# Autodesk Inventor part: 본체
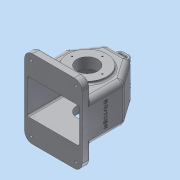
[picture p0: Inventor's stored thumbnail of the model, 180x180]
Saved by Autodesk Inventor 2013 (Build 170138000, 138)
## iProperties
Created: 2016-12
Part Number: 본체
Material: 알루미늄 6061
Document SubType Name: Modeling
Designer: dgall
Density: 2.71 g/cm^3
Mass: 1017.32 g
Surface Area: 1124 cm^2
Volume: 375.394 cm^3
Author: dgall
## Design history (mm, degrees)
sketch "스케치1"
  geometry: L1 (-55, -65)-(55, -65); L2 (55, -65)-(55, 15); L3 (55, 15)-(23.491, 60); L4 (23.491, 60)-(-23.491, 60); L5 (-23.491, 60)-(-55, 15); L6 (-55, 15)-(-55, -65); 2 further points
  constraints: 12 end point, 1 horizontal, 1 horizontal alignment, 1 midpoint, 1 parallel, 1 perpendicular, 1 vertical, 1 vertical alignment
  dimensions: "d0" = 35 deg angle of L6 L5; "d1" = 35 deg angle of L2 L3; "d2" = 80 distance from line of L2.end L1; "d4" = 125 distance between parallel lines of L1 L4; "d5" = 110 distance of L1.start L1.end; "d6" = 65 distance from line of L1 point (0, 0)
extrude "돌출1" new body sketch "스케치1" distance "d7" = 5; taper "d8" = 0 deg
sketch "스케치2"
  geometry: L1 (-55, -65)-(55, -65) reference; L2 (55, -65)-(55, 15) reference; L3 (55, 15)-(23.491, 60) reference; L4 (23.491, 60)-(-23.491, 60) reference; L5 (-23.491, 60)-(-55, 15) reference; L6 (-55, 15)-(-55, -65) reference; L7 (-55, -65)-(55, -65) reference; L8 (55, -65)-(55, 15) reference; L9 (55, 15)-(23.491, 60) reference; L10 (23.491, 60)-(-23.491, 60) reference; L11 (-23.491, 60)-(-55, 15) reference; L12 (-55, 15)-(-55, -65) reference; L13 (20.888, 55)-(50, 13.424); L14 (50, 13.424)-(50, -60); L15 (50, -60)-(-50, -60); L16 (-50, -60)-(-50, 13.424); L17 (-50, 13.424)-(-20.888, 55); L18 (-20.888, 55)-(20.888, 55); 1 further point
  constraints: 12 end point, 5 other
  dimensions: "d9" = 5 distance between parallel lines of L18 L4
extrude "돌출2" join sketch "스케치2" distance "d10" = 67; taper "d11" = 0 deg
sketch "스케치3"
  geometry: L1 (50, 13.424)-(50, -60) reference; L2 (50, -60)-(-50, -60) reference; L3 (-50, -60)-(-50, 13.424) reference; L4 (-50, 13.424)-(-20.888, 55) reference; L5 (-20.888, 55)-(20.888, 55) reference; L6 (20.888, 55)-(50, 13.424) reference; L7 (-55, -65)-(55, -65) reference; L8 (55, -65)-(55, 15) reference; L9 (55, 15)-(23.491, 60) reference; L10 (23.491, 60)-(-23.491, 60) reference; L11 (-23.491, 60)-(-55, 15) reference; L12 (-55, 15)-(-55, -65) reference; 1 further point
extrude "돌출3" join sketch "스케치3" distance "d12" = 5; taper "d13" = 0 deg
sketch "스케치4"
  geometry: L1 (50, -60)-(-50, -60) reference; L2 (-50, -60)-(-50, 13.424) reference; L3 (-50, 13.424)-(-20.888, 55) reference; L4 (-20.888, 55)-(20.888, 55) reference; L5 (20.888, 55)-(50, 13.424) reference; L6 (50, 13.424)-(50, -60) reference; L7 (-55, -65)-(55, -65) reference; L8 (55, -65)-(55, 15) reference; L9 (55, 15)-(23.491, 60) reference; L10 (23.491, 60)-(-23.491, 60) reference; L11 (-23.491, 60)-(-55, 15) reference; L12 (-55, 15)-(-55, -65) reference; L13 (-20.888, 55)-(20.888, 55); L14 (20.888, 55)-(50, 13.424); L15 (50, 13.424)-(50, -60); L16 (50, -60)-(-50, -60); L17 (-50, -60)-(-50, 13.424); L18 (-50, 13.424)-(-20.888, 55); 1 further point
  constraints: 12 end point, 5 other
  dimensions: "d14" = 5 distance between parallel lines of L13 L10
extrude "돌출4" join sketch "스케치4" distance "d15" = 5; taper "d16" = 0 deg
sketch "스케치5"
  geometry: L1 (0, 0)-(110, 0) reference; L2 (110, 0)-(110, 77) reference; L3 (0, 77)-(110, 77) reference; L4 (0, 0)-(0, 77) reference; L5 (105, 72)-(105, 5); L6 (105, 5)-(5, 5); L7 (5, 5)-(5, 72); L8 (5, 72)-(105, 72); 1 further point
  constraints: 8 end point, 3 other
  dimensions: "d17" = 5 distance between parallel lines of L8 L3
extrude "돌출5" cut sketch "스케치5" distance "d18" = 10; taper "d19" = 0 deg
sketch "스케치6"
  geometry: L1 (0, 0)-(110, 0) reference; L2 (110, 0)-(110, 77) reference; L3 (0, 77)-(110, 77) reference; L4 (0, 0)-(0, 77) reference; L5 (0, 113.5)-(110, 113.5); L6 (110, 113.5)-(110, -36.5); L7 (110, -36.5)-(0, -36.5); L8 (0, -36.5)-(0, 113.5); 5 further points
  constraints: 8 end point, 4 midpoint, 2 parallel, 1 coincident, 1 horizontal, 1 perpendicular, 1 vertical alignment
  dimensions: "d20" = 110 distance of L5.start L5.end; "d23" = 150 distance of L5.end L6.end
extrude "돌출6" join sketch "스케치6" distance "d24" = 15; taper "d25" = 0 deg
fillet "모깎기1" dims "d26" = 15
sketch "스케치7"
  geometry: L1 (0, -10)-(0, 82); L2 (0, 82)-(37.5, 82); L3 (60, 77)-(15, 77) reference; L4 (15, 77)-(-50, 77) reference; L5 (13.424, 72)-(-65, 72) reference; L6 (55, 72)-(13.424, 72) reference; L7 (55, 5)-(13.424, 5) reference; L8 (-65, 5)-(13.424, 5) reference; L9 (15, 0)-(-50, 0) reference; L10 (60, 0)-(15, 0) reference; L11 (37.5, 82)-(37.5, 77); L12 (37.5, 72)-(27, 61.5); L13 (27, 61.5)-(0, 61.5); L14 (37.5, 72)-(37.5, 77); L15 (31, 0)-(31, -10); L16 (31, -10)-(0, -10); L17 (31, 0)-(0, 0)
  constraints: 18 end point, 5 perpendicular, 4 point on line, 2 coincident, 1 collinear, 1 midpoint, 1 parallel, 1 vertical, 1 vertical alignment
  dimensions: "d27" = 75 diameter of L11 L1; "d30" = 54 diameter of L12.end L1; "d31" = 45 deg angle of L13 L12; "d32" = 5 distance between parallel lines of L2 L3; "d33" = 62 diameter of L15 L1; "d34" = 10 distance between parallel lines of L16 L9
revolve "회전1" sketch "스케치7" stored, may be unused: angle "d35" = 90 deg
sketch "스케치8"
  geometry: C1 r 31 at (0, 0); 1 further point
  constraints: 1 centre point, 1 coincident
  dimensions: "d36" = 62 diameter of C1
extrude "돌출7" join sketch "스케치8" distance "d38" = 10; taper "d39" = 0 deg
sketch "스케치9"
  geometry: C1 r 31 at (0, 0) reference; C2 r 20 at (0, 0)
  constraints: 1 centre point, 1 coincident
  dimensions: "d40" = 40 diameter of C2
extrude "돌출8" cut sketch "스케치9" distance "d42" = 15; taper "d43" = 0 deg
sketch "스케치10"
  geometry: C1 r 37.5 at (0, 0) reference; C2 r 20 at (0, 0)
  constraints: 1 centre point, 1 coincident
  dimensions: "d44" = 40 diameter of C2
extrude "돌출9" cut sketch "스케치10" distance "d46" = 24; taper "d47" = 0 deg
sketch "스케치11"
  geometry: C1 r 20 at (0, 0) reference; 1 further point
  constraints: 1 vertical alignment
  dimensions: "d48" = 26 distance of C1.centre point (0, 26)
hole "구멍1" sketch "스케치11" at (0, 26) diameter "d49" = 2.459; stored, may be unused: countersink angle "d53" = 90 deg, drill point angle "d55" = 118 deg; dims "d50" = 6, "d51" = 4, "d52" = 2, "d54" = 8
sketch "스케치12"
  geometry: C1 r 20 at (0, 0) reference; 1 further point
  constraints: 1 vertical alignment
  dimensions: "d59" = 29 distance of C1.centre point (0, 29)
hole "구멍2" sketch "스케치12" at (0, 29) diameter "d60" = 2.459; stored, may be unused: countersink angle "d64" = 90 deg, drill point angle "d66" = 118 deg; dims "d61" = 6, "d62" = 4, "d63" = 2, "d65" = 8
fillet "모깎기3" dims "d71" = 3
node "작업 평면1"
node "작업 평면2"
sketch "스케치13"
  geometry: L1 (-12, 15)-(-92, 15) reference; L2 (3, -120)-(3, 0) reference; L3 (-92, -135)-(-12, -135) reference; L4 (-107, -120)-(-107, 0) reference; L5 (-2, -26.5)-(-102, -26.5) reference; L6 (-102, -26.5)-(-102, -93.5) reference; L7 (-102, -93.5)-(-2, -93.5) reference; L8 (-2, -93.5)-(-2, -26.5) reference; A1 r 15 centre (-92, 0) between (-92, 15) and (-107, 0) reference; A2 r 15 centre (-12, 0) between (3, 0) and (-12, 15) reference; A3 r 15 centre (-12, -120) between (-12, -135) and (3, -120) reference; A4 r 15 centre (-92, -120) between (-107, -120) and (-92, -135) reference; 5 further points
  constraints: 2 horizontal alignment, 2 vertical alignment
  dimensions: "d74" = 12 distance from line of L4 point (-95, -123); "d75" = 12 distance from line of L3 point (-95, -123); "d76" = 12 distance from line of L1 point (-9, 3); "d77" = 12 distance from line of point (-9, 3) L2
hole "구멍3" sketch "스케치13" at (-95, -123), (-9, -123), (-9, 3), (-95, 3) diameter "d78" = 5; stored, may be unused: countersink angle "d82" = 90 deg, drill point angle "d84" = 0 deg; dims "d79" = 6, "d80" = 12, "d81" = 5, "d83" = 8
node "작업 평면4"
  node "작업 평면3"
sketch "스케치14"
  geometry: L1 (-19.326, 60)-(19.326, 60) reference; L2 (-12.5, 60)-(-12.5, 75); L3 (-12.5, 75)-(12.5, 75); L4 (12.5, 75)-(12.5, 60); L5 (-7.5, 60)-(-7.5, 70); L6 (-7.5, 70)-(7.5, 70); L7 (7.5, 70)-(7.5, 60); 3 further points
  constraints: 12 end point, 5 perpendicular, 4 point on line, 2 midpoint, 1 parallel, 1 vertical alignment
  dimensions: "d88" = 25 distance of L2.end L3.end; "d90" = 15 distance of L5.end L6.end; "d91" = 15 distance from line of L7.end L3; "d92" = 5 distance between parallel lines of L6 L3; "d93" = 5 distance between parallel lines of L4 L7
extrude "돌출10" join sketch "스케치14" distance "d94" = 8; taper "d95" = 0 deg
fillet "모깎기7" dims "d96" = 8
fillet "모깎기8" dims "d97" = 3
fillet "모깎기9" dims "d98" = 1
fillet "모깎기10" dims "d99" = 3
fillet "모깎기11" dims "d100" = 10
fillet "모깎기12" dims "d101" = 3
fillet "모깎기13" dims "d102" = 10
fillet "모깎기14" dims "d103" = 3
sketch "스케치15"
  geometry: L1 (120, 0)-(0, 0) reference; L2 (31.5, 76.847)-(88.5, 76.847) reference; 3 further points
  constraints: 1 midpoint, 1 vertical alignment, 1 other
  dimensions: "d104" = 45 distance from line of L1 point (60, 45)
extrude "돌출11" join sketch "스케치15" distance "d105" = 0.5; taper "d106" = 0 deg
node "솔리드1"
pattern_circular "원형 패턴1" dims angle "d57" = 360 deg
pattern_circular "원형 패턴2" dims angle "d68" = 360 deg
mirror "대칭1"
node "투영된 루프1"
node "투영된 루프2"
other parameters: "d86" = 38.5, "d87" = 18
